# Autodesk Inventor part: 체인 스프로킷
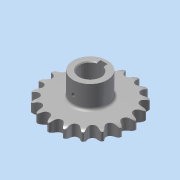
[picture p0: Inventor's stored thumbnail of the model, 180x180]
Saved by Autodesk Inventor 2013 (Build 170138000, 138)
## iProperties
Created: 2014-07
Part Number: 체인 스프로킷
Material: 일반
Document SubType Name: Modeling
Designer: KYOUNG IL JANG
Density: 1 g/cm^3
Mass: 94.0925 g
Surface Area: 236.854 cm^2
Volume: 94.0925 cm^3
Company: 한국ATC센터
Author: KYOUNG IL JANG
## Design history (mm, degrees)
sketch "이론적 톱니 프로파일"
  geometry: L1 (0, 0)-(0, 45.567); L2 (0, 0)-(14.795, 43.098); L3 (0, 45.567)-(14.795, 43.098); L4 (0, 45.567)-(5.661, 50.015); L5 (5.661, 50.015)-(-5.141, 45.406); L6 (-12.428, 43.493)-(-5.573, 46.417); L7 (-5.141, 45.406)-(-5.573, 46.417); L8 (5.573, 46.417)-(5.141, 45.406); L9 (0, 0)-(8.138, 48.771); A1 r 45.567 centre (0, 0) between (0, 45.567) and (14.795, 43.098); A2 r 49.445 centre (0, 0) between (7.302, 48.903) and (-7.302, 48.903); A3 r 4.545 centre (0, 45.567) between (-3.574, 42.758) and (3.574, 42.758); A4 r 7.453 centre (12.428, 43.493) between (7.302, 48.903) and (5.573, 46.417); A5 r 7.453 centre (-12.428, 43.493) between (-5.573, 46.417) and (-7.302, 48.903); A6 r 11.745 centre (5.661, 50.015) between (-5.141, 45.406) and (-3.574, 42.758); A7 r 11.745 centre (-5.661, 50.015) between (3.574, 42.758) and (5.141, 45.406); 2 further points
  constraints: 18 end point, 15 point on circle, 7 centre point, 3 coincident, 3 point on line, 3 symmetric about line, 3 tangent, 1 equal radius, 1 midpoint, 1 parallel, 1 vertical, 1 other
  dimensions: "d0" = 91.13301 diameter of A1 (computed from da_p, da_z); "d2" = 18.9474 deg angle of L2 L1 (computed from da_z); "d3" = 4.545 radius of A3 (= 0.5 x da_Dr + da_SC); "d10" = 128.158 deg angle of L4 L1 (computed from da_z); "d11" = 15.0526 deg angle of L5 L4 (computed from da_z); "d12" = 7.2 distance of L3.start L4.end (= 0.8 x da_Dr); "d13" = 11.745 distance of L4.end L5.end (= 1.3 x da_Dr + da_SC); "d14" = 12.6 distance of A4.centre L1.end (= 1.4 x da_Dr); "d23" = 4.5 distance from line of L9.end L3 (= da_Ha)
sketch "톱니 프로파일"
  geometry: L1 (0, 0)-(0, 45.567); L2 (0, 45.567)-(4.203, 43.837); L3 (0, 45.567)-(-4.203, 43.837); A1 r 4.545 centre (0, 45.567) between (-4.203, 43.837) and (4.203, 43.837); A2 r 22.68 centre (25.176, 35.206) between (7.12, 48.93) and (4.203, 43.837); A3 r 22.68 centre (-25.176, 35.206) between (-4.203, 43.837) and (-7.12, 48.93); A4 r 49.445 centre (0, 0) between (-7.12, 48.93) and (7.12, 48.93) reference; 1 further point
  constraints: 9 point on circle, 6 end point, 3 centre point, 2 tangent, 1 coincident, 1 equal radius, 1 vertical, 1 other
  dimensions: "d44" = 135.263 deg angle of L3 L2 (= da_Alfa); "d45" = 22.68 radius of A2 (= da_Re); "d46" = 4.545 radius of A1 (= da_Ri)
sketch "단면 프로파일"
  geometry: L1 (49.445, 0)-(-49.445, 0) reference; L2 (33.265, 6.65)-(-33.265, 6.65); L3 (-33.265, 6.65)-(-33.265, -6.65); L4 (-33.265, -6.65)-(33.265, -6.65); L5 (33.265, -6.65)-(33.265, 6.65); L6 (33.265, 6.65)-(49.445, 6.65); L7 (49.445, 6.65)-(49.445, -6.65); L8 (49.445, -6.65)-(33.265, -6.65); L9 (33.265, -6.65)-(33.265, 6.65); L10 (42.183, 6.65)-(0, 6.65); L11 (0, 6.65)-(0, -6.65); L12 (0, -6.65)-(42.183, -6.65); L13 (0, 6.65)-(0, -6.65); L14 (49.445, 4.775)-(49.445, -4.775); A1 r 15 centre (42.183, -8.35) between (49.445, 4.775) and (42.183, 6.65); A2 r 15 centre (42.183, 8.35) between (42.183, -6.65) and (49.445, -4.775); 2 further points
  constraints: 26 end point, 7 midpoint, 5 perpendicular, 4 parallel, 4 point on circle, 3 point on line, 3 symmetric about line, 2 centre point, 2 horizontal, 2 tangent, 1 collinear, 1 other
  dimensions: "d30" = 13.3 distance between parallel lines of L8 L6 (= da_Bf); "d31" = 66.53007 distance between parallel lines of L3 L5 (= da_Ds); "d32" = 13.3 distance between parallel lines of L4 L2 (= da_Bs); "d33" = 1.875 distance from line of L14.start L6 (= da_Ba); "d34" = 15 radius of A1 (= da_Rx); "d43" = 6.65 distance between parallel lines of L4 L1 (computed from da_k, da_pt, da_Bs)
revolve "슈라우드" stored, may be unused: angle "d36" = 90 deg
revolve "스트랜드" stored, may be unused: angle "d37" = 90 deg
extrude "이론적 톱니" cut sketch "이론적 톱니 프로파일" stored distance "d18" = 10; taper "d19" = 0 deg; dims "d49" = 0, "form_type" = 0 [user parameter]
extrude "톱니" cut sketch "톱니 프로파일" stored distance "d47" = 10; taper "d48" = 0 deg; dims "d50" = 10, "form_type" = 0 [user parameter]
node "타이밍 평면"
node "작업 평면3"
sketch "스케치5"
  geometry: C1 r 20 at (0, -45.567); 1 further point
  constraints: 1 centre point, 1 coincident
  dimensions: "d52" = 40 diameter of C1
extrude "돌출4" join sketch "스케치5" stored distance "d53" = 10; taper "d54" = 0 deg
sketch "스케치6"
  geometry: L1 (4, 11.843)-(4, 16.5); L2 (4, 16.5)-(-4, 16.5); L3 (-4, 16.5)-(-4, 11.843); A1 r 12.5 centre (0, 0) between (4, 11.843) and (-4, 11.843); 1 further point
  constraints: 6 end point, 2 parallel, 2 point on circle, 1 centre point, 1 coincident, 1 perpendicular, 1 vertical
  dimensions: "d55" = 25 diameter of A1; "d56" = 29 dimension on A1 L2 (computed from d55); "d57" = 8 distance of L1.end L2.end
extrude "돌출5" cut sketch "스케치6" stored distance "d58" = 10; taper "d59" = 0 deg
fillet "모깎기2" dims "d60" = 3
chamfer "모따기1" distance "d61" = 1; stored, may be unused: second distance "d62" = 2, angle "d63" = 45 deg
node "작업 평면4"
sketch "스케치7"
  geometry: L1 (-13.5, -13.3)-(13.5, -13.3) reference; 4 further points
  constraints: 1 vertical alignment
  dimensions: "d65" = 25 distance from line of point (0, 11.7) L1
hole "구멍1" sketch "스케치7" at (0, 11.7) diameter "d66" = 4.134; stored, may be unused: countersink angle "d70" = 90 deg, drill point angle "d72" = 118 deg; dims "d67" = 6, "d68" = 4, "d69" = 2, "d71" = 8
body "Solid1"
pattern_linear "스트랜드 패턴" dims "d40" = 24 (= da_pt)
pattern_circular "톱니 패턴" dims angle "d21" = 360 deg
other parameters: "da_p" = 15 [user parameter; used in 1 equation term], "da_Dr" = 9 [user parameter; used in 4 equation terms], "da_SC" = 0.045 [user parameter; used in 2 equation terms], "da_Ha" = 4.5 [user parameter; used in 1 equation term], "da_pt" = 24 [user parameter; used in 2 equation terms], "da_Bf" = 13.3 [user parameter; used in 1 equation term], "d28" = 0, "d29" = 0, "da_Ba" = 1.875 [user parameter; used in 1 equation term], "da_Rx" = 15 [user parameter; used in 1 equation term], "da_Ra" = 0.6 [user parameter], "da_Bs" = 13.3 [user parameter; used in 2 equation terms], "da_Ds" = 66.53007 [user parameter; used in 1 equation term], "d42" = 0, "da_Re" = 22.68 [user parameter; used in 1 equation term], "da_Ri" = 4.545 [user parameter; used in 1 equation term], "da_Alfa" = 135.263 deg [user parameter; used in 1 equation term]
